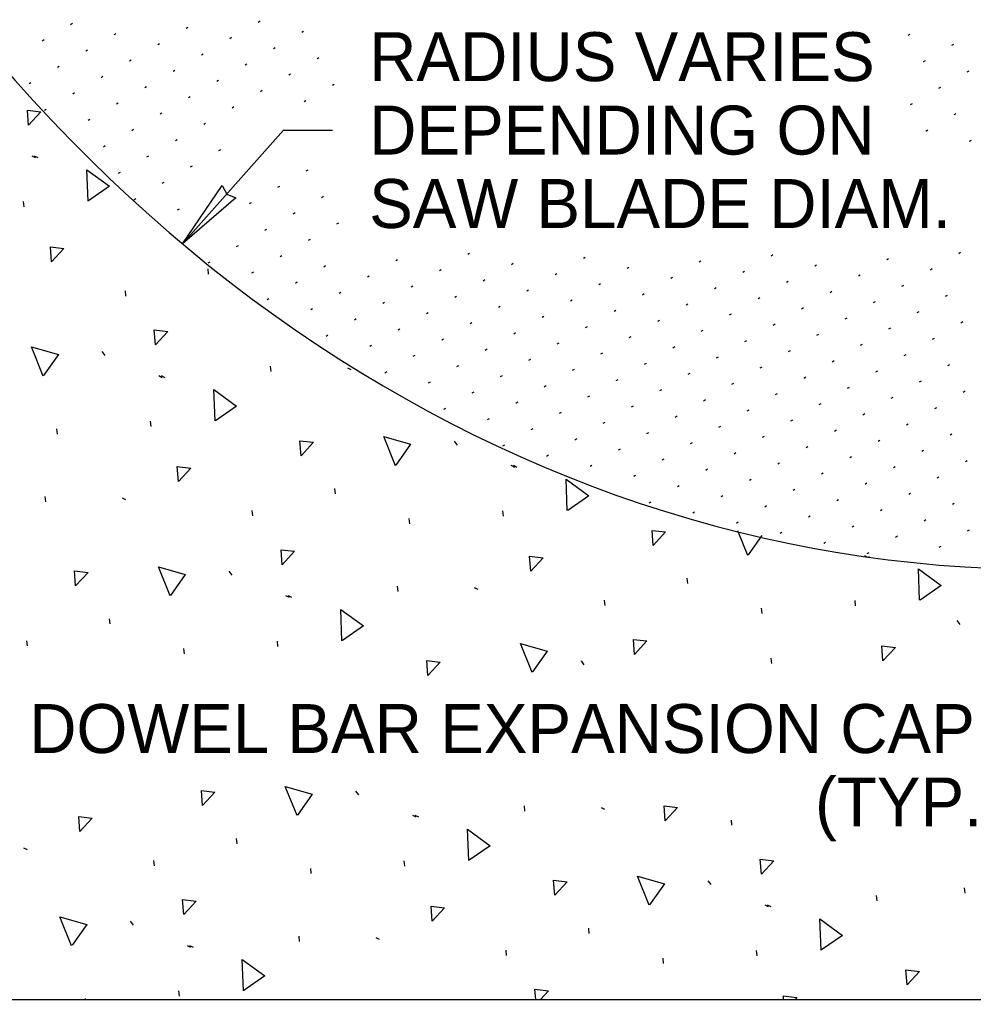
# Model space of a CAD drawing. Extents: x 99862 to 104211, y 98939 to 105076.
# Drawn here: x 100364.5 to 100676.3, y 103804.6 to 104124.9 of the extents above; entities that cross this region are included whole.
import ezdxf

# ---------------------------------------------------------------- set-up
doc = ezdxf.new("R2010")
doc.units = 0
for name, color, linetype in [('Level 1', 7, 'Continuous'), ('Level 15', 7, 'Continuous'), ('Level 20', 7, 'Continuous'), ('Level 3', 7, 'Continuous'), ('Level 4', 7, 'Continuous')]:
    doc.layers.add(name, color=color, linetype=linetype)

msp = doc.modelspace()

# ---------------------------------------------------------------- linework, layer by layer
at = {"layer": 'Level 1'}
msp.add_lwpolyline([(100169.63, 103804.62), (100694.77, 103804.62), (102647.84, 103804.62)], dxfattribs=at)
msp.add_ellipse((100698.76, 104535.63), major_axis=(0, -590.4), ratio=0.83118, start_param=5.208402, end_param=6.283185, dxfattribs=at)
msp.add_ellipse((100698.76, 104535.63), major_axis=(0, -590.4), ratio=0.83118, start_param=5.208402, end_param=6.283185, dxfattribs=at)
at = {"layer": 'Level 15'}
for p, q in [((100417.82, 104051.56), (100450.8, 104088.77)), ((100450.8, 104088.77), (100466.8, 104088.77))]:
    msp.add_line(p, q, dxfattribs=at)
msp.add_lwpolyline([(100417.82, 104051.56), (100430.73, 104070.62), (100432.26, 104067.85), (100435.19, 104066.66)], close=True, dxfattribs=at)
at = {"layer": 'Level 3'}
for p, q in [((100381.17, 104123.33), (100381.78, 104123.68)), ((100442.51, 104124.1), (100443.12, 104124.45)), ((100395.44, 104120.02), (100396.05, 104120.37)), ((100418.98, 104122.06), (100419.58, 104122.41)), ((100456.78, 104120.79), (100457.39, 104121.14)), ((100655.06, 104119.8), (100655.67, 104120.15)), ((100371.91, 104117.98), (100372.51, 104118.33)), ((100409.71, 104116.71), (100410.31, 104117.06)), ((100433.24, 104118.75), (100433.85, 104119.1)), ((100669.33, 104116.49), (100669.94, 104116.84)), ((100386.17, 104114.67), (100386.78, 104115.02)), ((100423.98, 104113.4), (100424.58, 104113.75)), ((100447.51, 104115.44), (100448.12, 104115.79)), ((100400.44, 104111.36), (100401.05, 104111.71)), ((100438.24, 104110.09), (100438.85, 104110.44)), ((100461.78, 104112.13), (100462.39, 104112.48)), ((100660.06, 104111.14), (100660.67, 104111.49)), ((100376.91, 104109.32), (100377.51, 104109.67)), ((100414.71, 104108.05), (100415.31, 104108.4)), ((100452.51, 104106.78), (100453.12, 104107.13)), ((100674.33, 104107.83), (100674.94, 104108.18)), ((100367.64, 104103.97), (100368.24, 104104.32)), ((100391.17, 104106.01), (100391.78, 104106.36)), ((100428.98, 104104.74), (100429.58, 104105.09)), ((100466.78, 104103.47), (100467.39, 104103.82)), ((100381.91, 104100.66), (100382.51, 104101.01)), ((100405.44, 104102.7), (100406.05, 104103.05)), ((100443.24, 104101.43), (100443.85, 104101.78)), ((100665.06, 104102.48), (100665.67, 104102.83)), ((100396.17, 104097.35), (100396.78, 104097.7)), ((100419.71, 104099.39), (100420.31, 104099.74)), ((100457.51, 104098.12), (100458.12, 104098.47)), ((100655.79, 104097.13), (100656.4, 104097.48)), ((100372.64, 104095.31), (100373.24, 104095.66)), ((100410.44, 104094.04), (100411.05, 104094.39)), ((100433.98, 104096.08), (100434.58, 104096.43)), ((100670.06, 104093.82), (100670.67, 104094.17)), ((100386.91, 104092), (100387.51, 104092.35)), ((100424.71, 104090.73), (100425.31, 104091.08)), ((100401.17, 104088.69), (100401.78, 104089.04)), ((100660.79, 104088.47), (100661.4, 104088.82)), ((100415.44, 104085.38), (100416.05, 104085.73)), ((100675.06, 104085.16), (100675.67, 104085.51)), ((100391.91, 104083.34), (100392.51, 104083.69)), ((100429.71, 104082.07), (100430.31, 104082.42)), ((100406.17, 104080.03), (100406.78, 104080.38)), ((100396.91, 104074.68), (100397.51, 104075.03)), ((100420.44, 104076.72), (100421.05, 104077.07)), ((100458.24, 104075.45), (100458.85, 104075.8)), ((100411.17, 104071.37), (100411.78, 104071.72)), ((100448.98, 104070.1), (100449.58, 104070.45)), ((100401.91, 104066.02), (100402.51, 104066.37)), ((100439.71, 104064.75), (100440.31, 104065.1)), ((100463.24, 104066.79), (100463.85, 104067.14)), ((100416.17, 104062.71), (100416.78, 104063.06)), ((100453.98, 104061.44), (100454.58, 104061.79)), ((100444.71, 104056.09), (100445.31, 104056.44)), ((100468.24, 104058.13), (100468.85, 104058.48)), ((100458.98, 104052.78), (100459.58, 104053.13)), ((100435.44, 104050.74), (100436.05, 104051.09)), ((100449.71, 104047.43), (100450.31, 104047.78)), ((100487.51, 104046.16), (100488.12, 104046.51)), ((100511.05, 104048.2), (100511.65, 104048.55)), ((100548.85, 104046.93), (100549.46, 104047.28)), ((100586.65, 104045.67), (100587.26, 104046.02)), ((100610.19, 104047.71), (100610.79, 104048.06)), ((100647.99, 104046.44), (100648.6, 104046.79)), ((100671.53, 104048.48), (100672.13, 104048.83)), ((100426.17, 104045.39), (100426.78, 104045.74)), ((100463.98, 104044.12), (100464.58, 104044.47)), ((100501.78, 104042.85), (100502.39, 104043.2)), ((100525.31, 104044.89), (100525.92, 104045.24)), ((100563.12, 104043.63), (100563.72, 104043.98)), ((100600.92, 104042.36), (100601.53, 104042.71)), ((100624.46, 104044.4), (100625.06, 104044.75)), ((100662.26, 104043.13), (100662.87, 104043.48)), ((100440.44, 104042.08), (100441.05, 104042.43)), ((100478.24, 104040.81), (100478.85, 104041.16)), ((100516.05, 104039.54), (100516.65, 104039.89)), ((100539.58, 104041.58), (100540.19, 104041.93)), ((100577.39, 104040.32), (100577.99, 104040.67)), ((100615.19, 104039.05), (100615.79, 104039.4)), ((100638.72, 104041.09), (100639.33, 104041.44)), ((100454.71, 104038.77), (100455.31, 104039.12)), ((100492.51, 104037.5), (100493.12, 104037.85)), ((100530.31, 104036.23), (100530.92, 104036.58)), ((100553.85, 104038.27), (100554.46, 104038.62)), ((100591.65, 104037.01), (100592.26, 104037.36)), ((100652.99, 104037.78), (100653.6, 104038.13)), ((100445.44, 104033.42), (100446.05, 104033.77)), ((100468.98, 104035.46), (100469.58, 104035.81)), ((100506.78, 104034.19), (100507.39, 104034.54)), ((100544.58, 104032.92), (100545.19, 104033.27)), ((100568.12, 104034.96), (100568.72, 104035.31)), ((100605.92, 104033.7), (100606.53, 104034.05)), ((100629.46, 104035.74), (100630.06, 104036.09)), ((100667.26, 104034.47), (100667.87, 104034.82)), ((100459.71, 104030.11), (100460.31, 104030.46)), ((100483.24, 104032.15), (100483.85, 104032.5)), ((100521.05, 104030.88), (100521.65, 104031.23)), ((100558.85, 104029.61), (100559.46, 104029.96)), ((100582.39, 104031.66), (100582.99, 104032.01)), ((100620.19, 104030.39), (100620.79, 104030.74)), ((100643.72, 104032.43), (100644.33, 104032.78)), ((100473.98, 104026.8), (100474.58, 104027.15)), ((100497.51, 104028.84), (100498.12, 104029.19)), ((100535.31, 104027.57), (100535.92, 104027.92)), ((100573.12, 104026.3), (100573.72, 104026.65)), ((100596.65, 104028.35), (100597.26, 104028.7)), ((100634.46, 104027.08), (100635.06, 104027.43)), ((100657.99, 104029.12), (100658.6, 104029.47)), ((100488.24, 104023.49), (100488.85, 104023.84)), ((100511.78, 104025.53), (100512.39, 104025.88)), ((100549.58, 104024.26), (100550.19, 104024.61)), ((100610.92, 104025.04), (100611.53, 104025.39)), ((100648.72, 104023.77), (100649.33, 104024.12)), ((100672.26, 104025.81), (100672.87, 104026.16)), ((100464.71, 104021.45), (100465.31, 104021.8)), ((100502.51, 104020.18), (100503.12, 104020.53)), ((100526.05, 104022.22), (100526.65, 104022.57)), ((100563.85, 104020.95), (100564.46, 104021.3)), ((100587.39, 104023), (100587.99, 104023.35)), ((100625.19, 104021.73), (100625.79, 104022.08)), ((100662.99, 104020.46), (100663.6, 104020.81)), ((100478.98, 104018.14), (100479.58, 104018.49)), ((100516.78, 104016.87), (100517.39, 104017.22)), ((100540.31, 104018.91), (100540.92, 104019.26)), ((100578.12, 104017.64), (100578.72, 104017.99)), ((100601.65, 104019.69), (100602.26, 104020.04)), ((100639.46, 104018.42), (100640.06, 104018.77)), ((100493.24, 104014.83), (100493.85, 104015.18)), ((100531.05, 104013.56), (100531.65, 104013.91)), ((100554.58, 104015.6), (100555.19, 104015.95)), ((100592.39, 104014.33), (100592.99, 104014.68)), ((100615.92, 104016.38), (100616.53, 104016.73)), ((100653.72, 104015.11), (100654.33, 104015.46)), ((100507.51, 104011.52), (100508.12, 104011.87)), ((100545.31, 104010.25), (100545.92, 104010.6)), ((100568.85, 104012.29), (100569.46, 104012.64)), ((100606.65, 104011.03), (100607.26, 104011.38)), ((100630.19, 104013.07), (100630.79, 104013.42)), ((100667.99, 104011.8), (100668.6, 104012.15)), ((100483.98, 104009.48), (100484.58, 104009.83)), ((100521.78, 104008.21), (100522.39, 104008.56)), ((100583.12, 104008.98), (100583.72, 104009.33)), ((100620.92, 104007.72), (100621.53, 104008.07)), ((100644.46, 104009.76), (100645.06, 104010.11)), ((100498.24, 104006.17), (100498.85, 104006.52)), ((100536.05, 104004.9), (100536.65, 104005.25)), ((100559.58, 104006.94), (100560.19, 104007.29)), ((100597.39, 104005.67), (100597.99, 104006.02)), ((100635.19, 104004.41), (100635.79, 104004.76)), ((100658.72, 104006.45), (100659.33, 104006.8)), ((100512.51, 104002.86), (100513.12, 104003.21)), ((100550.31, 104001.59), (100550.92, 104001.94)), ((100573.85, 104003.63), (100574.46, 104003.98)), ((100611.65, 104002.37), (100612.26, 104002.72)), ((100649.46, 104001.1), (100650.06, 104001.45)), ((100672.99, 104003.14), (100673.6, 104003.49)), ((100503.24, 103997.51), (100503.85, 103997.86)), ((100526.78, 103999.55), (100527.39, 103999.9)), ((100564.58, 103998.28), (100565.19, 103998.63)), ((100588.12, 104000.32), (100588.72, 104000.67)), ((100625.92, 103999.06), (100626.53, 103999.41)), ((100663.72, 103997.79), (100664.33, 103998.14)), ((100517.51, 103994.2), (100518.12, 103994.55)), ((100541.05, 103996.24), (100541.65, 103996.59)), ((100578.85, 103994.97), (100579.46, 103995.32)), ((100602.39, 103997.01), (100602.99, 103997.36)), ((100640.19, 103995.75), (100640.79, 103996.1)), ((100555.31, 103992.93), (100555.92, 103993.28)), ((100593.12, 103991.66), (100593.72, 103992.01)), ((100616.65, 103993.7), (100617.26, 103994.05)), ((100654.46, 103992.44), (100655.06, 103992.79)), ((100531.78, 103990.89), (100532.39, 103991.24)), ((100569.58, 103989.62), (100570.19, 103989.97)), ((100607.39, 103988.35), (100607.99, 103988.7)), ((100630.92, 103990.4), (100631.53, 103990.75)), ((100668.72, 103989.13), (100669.33, 103989.48)), ((100522.51, 103985.54), (100523.12, 103985.89)), ((100546.05, 103987.58), (100546.65, 103987.93)), ((100583.85, 103986.31), (100584.46, 103986.66)), ((100621.65, 103985.04), (100622.26, 103985.39)), ((100645.19, 103987.09), (100645.79, 103987.44)), ((100536.78, 103982.23), (100537.39, 103982.58)), ((100560.31, 103984.27), (100560.92, 103984.62)), ((100598.12, 103983), (100598.72, 103983.35)), ((100635.92, 103981.74), (100636.53, 103982.09)), ((100659.46, 103983.78), (100660.06, 103984.13)), ((100551.05, 103978.92), (100551.65, 103979.27)), ((100574.58, 103980.96), (100575.19, 103981.31)), ((100612.39, 103979.69), (100612.99, 103980.04)), ((100650.19, 103978.43), (100650.79, 103978.78)), ((100673.72, 103980.47), (100674.33, 103980.82)), ((100565.31, 103975.61), (100565.92, 103975.96)), ((100588.85, 103977.65), (100589.46, 103978)), ((100626.65, 103976.38), (100627.26, 103976.73)), ((100664.46, 103975.12), (100665.06, 103975.47)), ((100579.58, 103972.3), (100580.19, 103972.65)), ((100603.12, 103974.34), (100603.72, 103974.69)), ((100640.92, 103973.07), (100641.53, 103973.42)), ((100593.85, 103968.99), (100594.46, 103969.34)), ((100617.39, 103971.03), (100617.99, 103971.38)), ((100655.19, 103969.77), (100655.79, 103970.12)), ((100570.31, 103966.95), (100570.92, 103967.3)), ((100608.12, 103965.68), (100608.72, 103966.03)), ((100631.65, 103967.72), (100632.26, 103968.07)), ((100669.46, 103966.46), (100670.06, 103966.81)), ((100584.58, 103963.64), (100585.19, 103963.99)), ((100622.39, 103962.37), (100622.99, 103962.72)), ((100645.92, 103964.41), (100646.53, 103964.76)), ((100598.85, 103960.33), (100599.46, 103960.68)), ((100636.65, 103959.06), (100637.26, 103959.41)), ((100660.19, 103961.1), (100660.79, 103961.45)), ((100613.12, 103957.02), (100613.72, 103957.37)), ((100650.92, 103955.75), (100651.53, 103956.1)), ((100674.46, 103957.8), (100675.06, 103958.15)), ((100627.39, 103953.71), (100627.99, 103954.06)), ((100641.65, 103950.4), (100642.26, 103950.75)), ((100665.19, 103952.44), (100665.79, 103952.79))]:
    msp.add_line(p, q, dxfattribs=at)
at = {"layer": 'Level 4'}
for p, q in [((100368.52, 104080.36), (100369.67, 104079.79)), ((100369.34, 104080.37), (100370.48, 104079.8)), ((100366.03, 104063.72), (100365.84, 104065.46)), ((100426.31, 104041.72), (100426.13, 104043.46)), ((100399.29, 104034.53), (100399.11, 104036.27)), ((100391.43, 104016.43), (100392.38, 104015.14)), ((100446.77, 104009.83), (100446.59, 104011.57)), ((100471.68, 104011.08), (100472.83, 104010.52)), ((100410, 104008.51), (100411.15, 104007.95)), ((100410.82, 104008.52), (100411.97, 104007.95)), ((100407.51, 103991.87), (100407.32, 103993.61)), ((100376.93, 103989.42), (100376.75, 103991.16)), ((100506.59, 103987.12), (100507.54, 103985.83)), ((100525.16, 103979.2), (100526.31, 103978.64)), ((100525.98, 103979.21), (100527.12, 103978.64)), ((100373.1, 103967.29), (100372.91, 103969.03)), ((100467.79, 103969.87), (100467.61, 103971.61)), ((100398.01, 103968.55), (100399.15, 103967.98)), ((100440.77, 103962.68), (100440.59, 103964.42)), ((100522.67, 103962.56), (100522.48, 103964.3)), ((100492.09, 103960.11), (100491.9, 103961.85)), ((100640.71, 103949.7), (100641.47, 103949.33)), ((100642.08, 103949.43), (100642.28, 103949.33)), ((100432.91, 103944.58), (100433.87, 103943.29)), ((100582.95, 103940.56), (100582.77, 103942.3)), ((100488.26, 103937.98), (100488.07, 103939.72)), ((100513.16, 103939.24), (100514.31, 103938.67)), ((100451.48, 103936.67), (100452.63, 103936.1)), ((100452.3, 103936.67), (100453.45, 103936.1)), ((100555.93, 103933.37), (100555.75, 103935.11)), ((100637.82, 103933.25), (100637.64, 103934.99)), ((100607.25, 103930.8), (100607.06, 103932.54)), ((100394.11, 103927.33), (100393.93, 103929.07)), ((100670.91, 103928.5), (100671.86, 103927.2)), ((100367.09, 103920.14), (100366.91, 103921.88)), ((100448.99, 103920.02), (100448.8, 103921.76)), ((100418.41, 103917.57), (100418.23, 103919.31)), ((100548.07, 103915.27), (100549.02, 103913.98)), ((100610.4, 103914.43), (100610.22, 103916.17)), ((100474.39, 103872.73), (100475.35, 103871.44)), ((100529.74, 103866.13), (100529.55, 103867.87)), ((100554.65, 103867.39), (100555.79, 103866.82)), ((100492.96, 103864.82), (100494.11, 103864.25)), ((100493.78, 103864.82), (100494.93, 103864.25)), ((100597.41, 103861.52), (100597.23, 103863.26)), ((100435.6, 103855.49), (100435.41, 103857.23)), ((100365.81, 103854.16), (100366.96, 103853.59)), ((100408.58, 103848.29), (100408.39, 103850.03)), ((100459.89, 103845.73), (100459.71, 103847.46)), ((100490.47, 103848.18), (100490.29, 103849.92)), ((100589.55, 103843.42), (100590.51, 103842.13)), ((100673.59, 103839.4), (100673.41, 103841.14)), ((100644.9, 103836.82), (100644.71, 103838.56)), ((100608.12, 103835.51), (100609.27, 103834.94)), ((100608.94, 103835.51), (100610.09, 103834.94)), ((100400.72, 103830.2), (100401.67, 103828.9)), ((100456.06, 103823.59), (100455.88, 103825.33)), ((100480.97, 103824.85), (100482.12, 103824.28)), ((100550.75, 103826.17), (100550.57, 103827.91)), ((100419.29, 103822.28), (100420.43, 103821.71)), ((100420.1, 103822.29), (100421.25, 103821.72)), ((100523.73, 103818.98), (100523.55, 103820.72)), ((100605.63, 103818.87), (100605.44, 103820.61)), ((100575.05, 103816.41), (100574.87, 103818.15)), ((100416.79, 103805.64), (100416.61, 103807.38)), ((100386.06, 103804.62), (100386.03, 103804.93))]:
    msp.add_line(p, q, dxfattribs=at)
for points in [[(100367.44, 104090.4), (100367.07, 104095.31), (100371.47, 104094.78), (100367.44, 104090.4)], [(100386.93, 104065.53), (100386.55, 104075.78), (100393.95, 104070.41), (100387.08, 104065.62)], [(100374.98, 104045.72), (100374.61, 104050.63), (100379.02, 104050.1), (100374.98, 104045.72)], [(100408.92, 104018.56), (100408.55, 104023.47), (100412.96, 104022.94), (100408.92, 104018.56)], [(100372.26, 104008.39), (100368.41, 104017.89), (100377.2, 104015.38), (100372.38, 104008.53)], [(100428.41, 103993.69), (100428.03, 104003.93), (100435.43, 103998.56), (100428.56, 103993.77)], [(100487.42, 103979.08), (100483.57, 103988.58), (100492.36, 103986.07), (100487.54, 103979.22)], [(100456.53, 103982.34), (100456.15, 103987.25), (100460.56, 103986.72), (100456.53, 103982.34)], [(100416.47, 103973.87), (100416.09, 103978.78), (100420.5, 103978.25), (100416.47, 103973.87)], [(100543.57, 103964.38), (100543.19, 103974.62), (100550.59, 103969.25), (100543.72, 103964.46)], [(100571.69, 103953.03), (100571.31, 103957.94), (100575.72, 103957.41), (100571.69, 103953.03)], [(100602.58, 103949.77), (100599.33, 103957.79)], [(100607.16, 103956.26), (100602.69, 103949.91)], [(100450.4, 103946.71), (100450.03, 103951.62), (100454.44, 103951.09), (100450.4, 103946.71)], [(100531.62, 103944.56), (100531.25, 103949.47), (100535.66, 103948.94), (100531.62, 103944.56)], [(100382.85, 103939.81), (100382.48, 103944.72), (100386.89, 103944.18), (100382.85, 103939.81)], [(100413.75, 103936.55), (100409.89, 103946.04), (100418.68, 103943.53), (100413.86, 103936.68)], [(100658.72, 103935.07), (100658.35, 103945.31), (100665.75, 103939.94), (100658.88, 103935.15)], [(100469.89, 103921.84), (100469.51, 103932.08), (100476.92, 103926.72), (100470.04, 103921.93)], [(100532.1, 103911.51), (100528.25, 103921), (100537.04, 103918.49), (100532.22, 103911.64)], [(100565.56, 103917.4), (100565.19, 103922.31), (100569.6, 103921.78), (100565.56, 103917.4)], [(100646.78, 103915.25), (100646.41, 103920.16), (100650.82, 103919.63), (100646.78, 103915.25)], [(100498.01, 103910.49), (100497.64, 103915.41), (100502.04, 103914.87), (100498.01, 103910.49)], [(100424.33, 103867.96), (100423.96, 103872.87), (100428.37, 103872.34), (100424.33, 103867.96)], [(100455.23, 103864.7), (100451.37, 103874.19), (100460.16, 103871.68), (100455.34, 103864.83)], [(100575.59, 103862.95), (100575.22, 103867.86), (100579.62, 103867.32), (100575.59, 103862.95)], [(100384.27, 103859.49), (100383.89, 103864.4), (100388.3, 103863.86), (100384.27, 103859.49)], [(100511.37, 103849.99), (100510.99, 103860.23), (100518.4, 103854.87), (100511.52, 103850.08)], [(100607.04, 103845.55), (100606.67, 103850.46), (100611.08, 103849.93), (100607.04, 103845.55)], [(100570.39, 103835.39), (100566.53, 103844.88), (100575.32, 103842.37), (100570.5, 103835.52)], [(100539.49, 103838.65), (100539.12, 103843.56), (100543.53, 103843.03), (100539.49, 103838.65)], [(100418.21, 103832.32), (100417.83, 103837.23), (100422.24, 103836.7), (100418.21, 103832.32)], [(100499.43, 103830.17), (100499.05, 103835.09), (100503.46, 103834.55), (100499.43, 103830.17)], [(100381.55, 103822.16), (100377.69, 103831.66), (100386.49, 103829.15), (100381.66, 103822.3)], [(100626.53, 103820.68), (100626.15, 103830.92), (100633.56, 103825.56), (100626.68, 103820.77)], [(100437.69, 103807.45), (100437.32, 103817.69), (100444.72, 103812.33), (100437.85, 103807.54)], [(100654.65, 103809.34), (100654.28, 103814.25), (100658.68, 103813.72), (100654.65, 103809.34)], [(100533.24, 103804.62), (100532.99, 103807.92), (100537.4, 103807.39), (100534.85, 103804.62)], [(100614.3, 103804.62), (100614.21, 103805.78), (100618.62, 103805.24), (100618.05, 103804.62)]]:
    msp.add_lwpolyline(points, dxfattribs=at)

# ---------------------------------------------------------------- texts
at = {"layer": 'Level 20'}
for s, p in [('RADIUS VARIES', (100478.8, 104104.77)), ('DEPENDING ON', (100478.8, 104080.77)), ('SAW BLADE DIAM.', (100478.8, 104056.77)), ('DOWEL BAR EXPANSION CAP', (100367.67, 103885.15)), ('(TYP.)', (100624.57, 103861.15))]:
    msp.add_text(s, height=16, dxfattribs=at).set_placement(p)

doc.saveas('drawing.dxf')
